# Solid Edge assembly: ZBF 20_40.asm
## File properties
Title: Zylinder
Author: bmolnar
Template: iso metric assembly.asm
Last saved by: bmolnar
Revision: 12
Application: Solid Edge
Username: bmolnar
Dokumentum tartalom típus: 1
Document Number: ZBF 20/40
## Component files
Profilrohr.par
Kolbenstange.par
Kit.par
Mutter.par
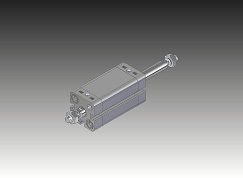
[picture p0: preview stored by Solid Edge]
